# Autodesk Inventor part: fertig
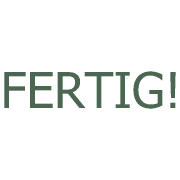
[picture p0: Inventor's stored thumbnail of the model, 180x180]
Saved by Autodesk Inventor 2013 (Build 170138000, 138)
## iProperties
Created: 2010-08
Part Number: fertig
Document SubType Name: Modeling
Designer: juergen
Density: 1 g/cm^3
Material: Allgemein
Author: juergen
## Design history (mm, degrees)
sketch "Skizze2"
  geometry: L1 (-33.361, 17.857)-(35.042, 17.857); L2 (35.042, 17.857)-(35.042, -14.328); L3 (35.042, -14.328)-(-33.361, -14.328); L4 (-33.361, -14.328)-(-33.361, 17.857); 1 further point
  constraints: 2 other
extrude "Extrusion1" new body sketch "Skizze2" distance "d0" = 10; taper "d1" = 0 deg
node "Volumenkörper1"
node "Volumenkörpern"
node "Oberflächenkörpern"
